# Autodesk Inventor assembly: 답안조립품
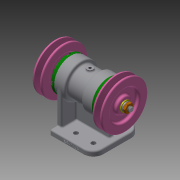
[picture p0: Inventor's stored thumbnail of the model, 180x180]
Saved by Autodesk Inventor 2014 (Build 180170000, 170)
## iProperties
Created: 2020-06
Part Number: 답안조립품
Document SubType Name: Assembly
Designer: kh
Author: kh
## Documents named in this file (12)
- C:\Users\kh\Desktop\700606V1031 (1)\답안조립품.iam
- C:\Users\kh\Desktop\700606V1031 (1)\본체.ipt
- C:\Users\kh\Desktop\700606V1031 (1)\축.ipt
- C:\Users\kh\Desktop\700606V1031 (1)\베어링 6204.ipt
- C:\Users\kh\Desktop\700606V1031 (1)\키 5x5x12.ipt
- C:\Users\kh\Desktop\700606V1031 (1)\오일 실 20 32 5.ipt
- C:\Users\kh\Desktop\700606V1031 (1)\커버.ipt
- C:\Users\kh\Desktop\700606V1031 (1)\V-벨트풀리.ipt
- C:\Users\kh\Desktop\700606V1031 (1)\너트 M10.ipt
- C:\Users\kh\Desktop\700606V1031 (1)\스프링 와셔 10.ipt
- C:\Users\kh\Desktop\700606V1031 (1)\평면 와셔 10x21.ipt
- C:\Users\kh\Desktop\700606V1031 (1)\볼트 M4.ipt
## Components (2 placed, 1 different names)
1. V-벨트풀리:1 — Mate:26, Mate:27, Mate:28, Mate:30
2. V-벨트풀리:2 — Mate:35, Mate:36, Mate:37, Mate:39
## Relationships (8: Mate 8)
- Mate:26: V-벨트풀리:1
- Mate:27: V-벨트풀리:1
- Mate:28: V-벨트풀리:1
- Mate:30: V-벨트풀리:1
- Mate:35: V-벨트풀리:2
- Mate:36: V-벨트풀리:2
- Mate:37: V-벨트풀리:2
- Mate:39: V-벨트풀리:2
